// Mitsubishi GX Works2 project: 实例训练(搬运)   PLC: FX3U/FX3UC

PROGRAM MAIN
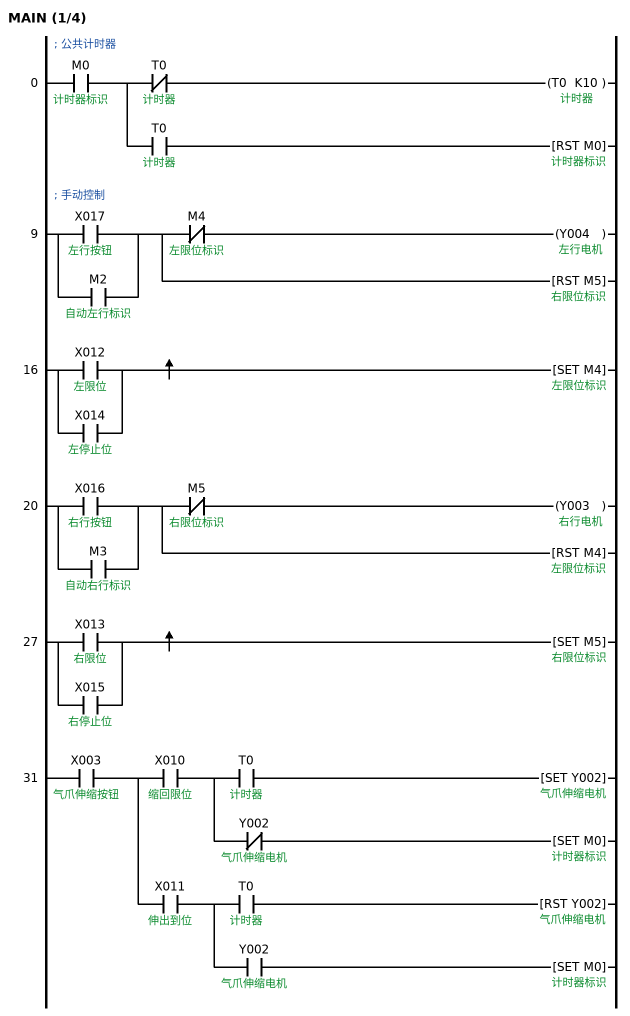
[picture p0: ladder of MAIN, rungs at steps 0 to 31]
; 公共计时器
0     LD      M0  ; 计时器标识
      MPS
      ANI     T0  ; 计时器
      OUT     T0 K10  ; 计时器
      MPP
      AND     T0  ; 计时器
      RST     M0  ; 计时器标识
; 手动控制
9     LD      X017  ; 左行按钮
      OR      M2  ; 自动左行标识
      MPS
      ANI     M4  ; 左限位标识
      OUT     Y004  ; 左行电机
      MPP
      RST     M5  ; 右限位标识
16    LD      X012  ; 左限位
      OR      X014  ; 左停止位
      MEP
      SET     M4  ; 左限位标识
20    LD      X016  ; 右行按钮
      OR      M3  ; 自动右行标识
      MPS
      ANI     M5  ; 右限位标识
      OUT     Y003  ; 右行电机
      MPP
      RST     M4  ; 左限位标识
27    LD      X013  ; 右限位
      OR      X015  ; 右停止位
      MEP
      SET     M5  ; 右限位标识
31    LD      X003  ; 气爪伸缩按钮
      MPS
      AND     X010  ; 缩回限位
      MPS
      AND     T0  ; 计时器
      SET     Y002  ; 气爪伸缩电机
      MPP
      ANI     Y002  ; 气爪伸缩电机
      SET     M0  ; 计时器标识
        [note] 伸缩间隔1秒
      MPP
      AND     X011  ; 伸出到位
      MPS
      AND     T0  ; 计时器
      RST     Y002  ; 气爪伸缩电机
      MPP
      AND     Y002  ; 气爪伸缩电机
      SET     M0  ; 计时器标识
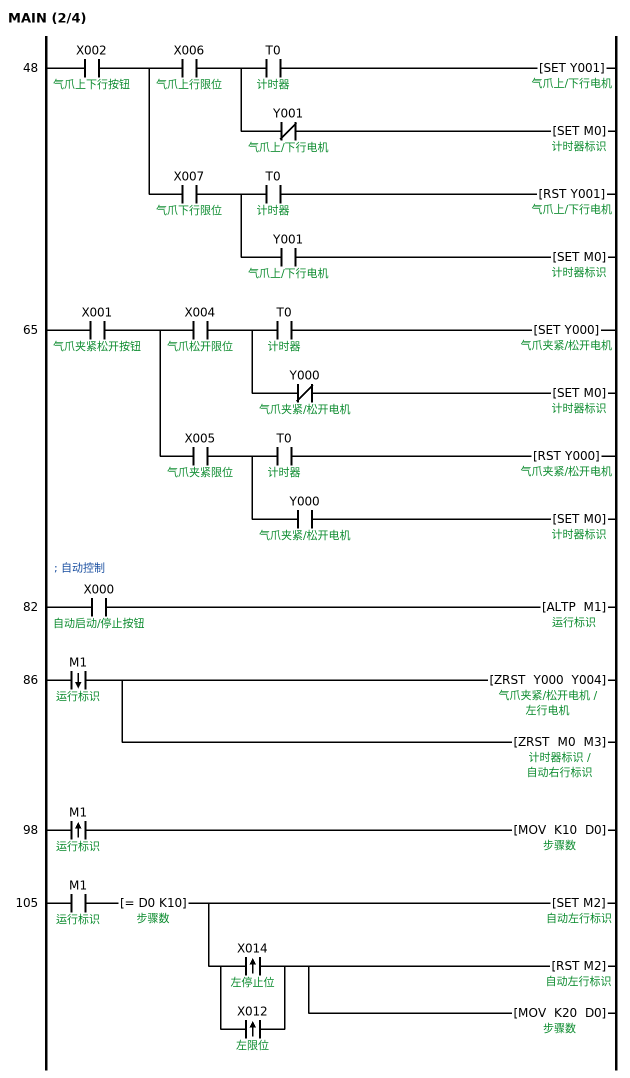
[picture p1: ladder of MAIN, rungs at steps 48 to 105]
48    LD      X002  ; 气爪上下行按钮
      MPS
      AND     X006  ; 气爪上行限位
      MPS
      AND     T0  ; 计时器
      SET     Y001  ; 气爪上/下行电机
      MPP
      ANI     Y001  ; 气爪上/下行电机
      SET     M0  ; 计时器标识
      MPP
      AND     X007  ; 气爪下行限位
      MPS
      AND     T0  ; 计时器
      RST     Y001  ; 气爪上/下行电机
      MPP
      AND     Y001  ; 气爪上/下行电机
      SET     M0  ; 计时器标识
65    LD      X001  ; 气爪夹紧松开按钮
      MPS
      AND     X004  ; 气爪松开限位
      MPS
      AND     T0  ; 计时器
      SET     Y000  ; 气爪夹紧/松开电机
      MPP
      ANI     Y000  ; 气爪夹紧/松开电机
      SET     M0  ; 计时器标识
      MPP
      AND     X005  ; 气爪夹紧限位
      MPS
      AND     T0  ; 计时器
      RST     Y000  ; 气爪夹紧/松开电机
      MPP
      AND     Y000  ; 气爪夹紧/松开电机
      SET     M0  ; 计时器标识
; 自动控制
82    LD      X000  ; 自动启动/停止按钮
      ALTP    M1  ; 运行标识
86    LDF     M1  ; 运行标识
      ZRST    Y000 Y004
      ZRST    M0 M3
98    LDP     M1  ; 运行标识
      MOV     K10 D0  ; 步骤数
105   LD      M1  ; 运行标识
      AND=    D0 K10  ; 步骤数
      SET     M2  ; 自动左行标识
        [note] 1.左行
      LDP     X014  ; 左停止位
      ORP     X012  ; 左限位
      ANB
      RST     M2  ; 自动左行标识
      MOV     K20 D0
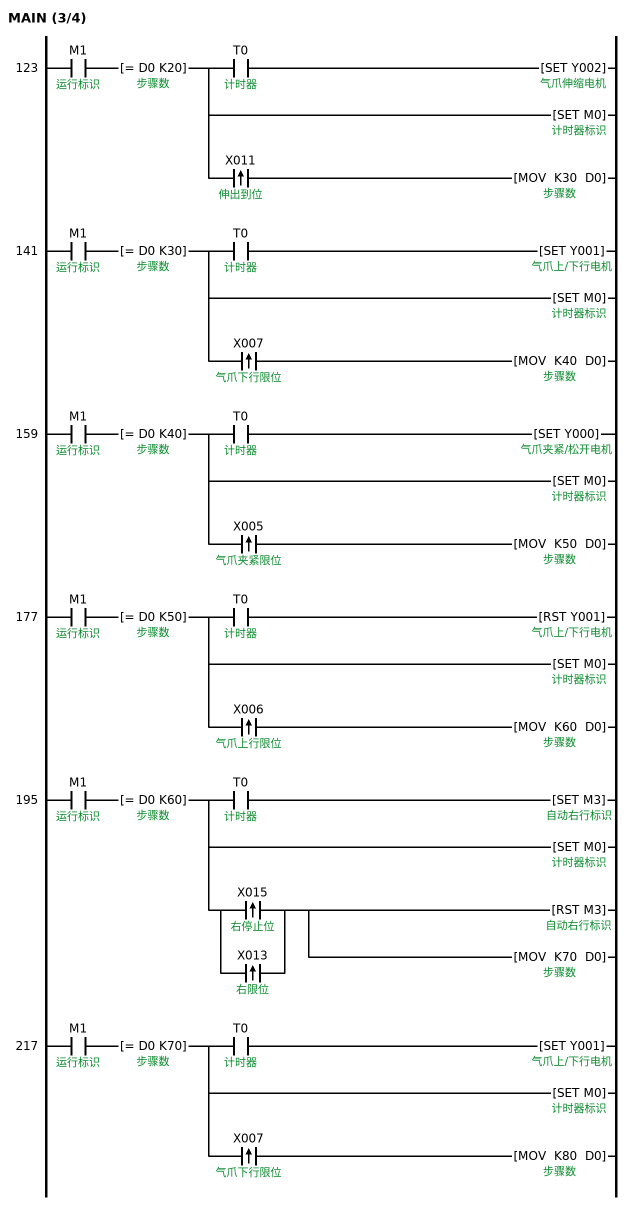
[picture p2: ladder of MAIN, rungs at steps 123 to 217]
123   LD      M1  ; 运行标识
      AND=    D0 K20  ; 步骤数
      MPS
      AND     T0  ; 计时器
      SET     Y002  ; 气爪伸缩电机
        [note] 2.气爪伸出
      MPP
      SET     M0  ; 计时器标识
      ANDP    X011  ; 伸出到位
      MOV     K30 D0
141   LD      M1  ; 运行标识
      AND=    D0 K30  ; 步骤数
      MPS
      AND     T0  ; 计时器
      SET     Y001  ; 气爪上/下行电机
        [note] 3.气爪下行
      MPP
      SET     M0  ; 计时器标识
      ANDP    X007  ; 气爪下行限位
      MOV     K40 D0
159   LD      M1  ; 运行标识
      AND=    D0 K40  ; 步骤数
      MPS
      AND     T0  ; 计时器
      SET     Y000  ; 气爪夹紧/松开电机
        [note] 4.夹紧
      MPP
      SET     M0  ; 计时器标识
      ANDP    X005  ; 气爪夹紧限位
      MOV     K50 D0
177   LD      M1  ; 运行标识
      AND=    D0 K50  ; 步骤数
      MPS
      AND     T0  ; 计时器
      RST     Y001  ; 气爪上/下行电机
        [note] 5.气爪上行
      MPP
      SET     M0  ; 计时器标识
      ANDP    X006  ; 气爪上行限位
      MOV     K60 D0
195   LD      M1  ; 运行标识
      AND=    D0 K60  ; 步骤数
      MPS
      AND     T0  ; 计时器
      SET     M3  ; 自动右行标识
        [note] 6.右行
      MPP
      SET     M0  ; 计时器标识
      LDP     X015  ; 右停止位
      ORP     X013  ; 右限位
      ANB
      RST     M3  ; 自动右行标识
      MOV     K70 D0
217   LD      M1  ; 运行标识
      AND=    D0 K70  ; 步骤数
      MPS
      AND     T0  ; 计时器
      SET     Y001  ; 气爪上/下行电机
        [note] 7.气爪下行
      MPP
      SET     M0  ; 计时器标识
      ANDP    X007  ; 气爪下行限位
      MOV     K80 D0
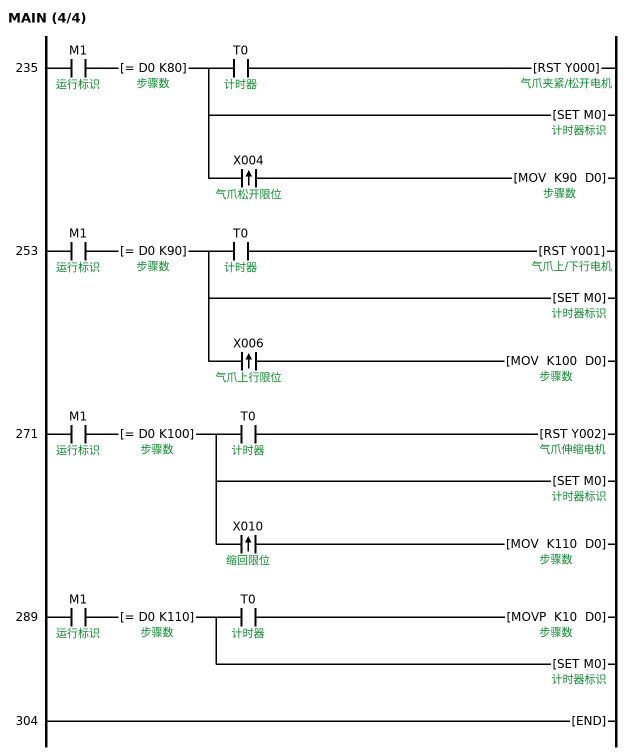
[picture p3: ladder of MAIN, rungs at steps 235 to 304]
235   LD      M1  ; 运行标识
      AND=    D0 K80  ; 步骤数
      MPS
      AND     T0  ; 计时器
      RST     Y000  ; 气爪夹紧/松开电机
        [note] 8.松开
      MPP
      SET     M0  ; 计时器标识
      ANDP    X004  ; 气爪松开限位
      MOV     K90 D0
253   LD      M1  ; 运行标识
      AND=    D0 K90  ; 步骤数
      MPS
      AND     T0  ; 计时器
      RST     Y001  ; 气爪上/下行电机
        [note] 9.气爪上行
      MPP
      SET     M0  ; 计时器标识
      ANDP    X006  ; 气爪上行限位
      MOV     K100 D0
271   LD      M1  ; 运行标识
      AND=    D0 K100  ; 步骤数
      MPS
      AND     T0  ; 计时器
      RST     Y002  ; 气爪伸缩电机
        [note] 10.气爪缩回
      MPP
      SET     M0  ; 计时器标识
      ANDP    X010  ; 缩回限位
      MOV     K110 D0
289   LD      M1  ; 运行标识
      AND=    D0 K110  ; 步骤数
      MPS
      AND     T0  ; 计时器
      MOVP    K10 D0
        [note] 11.回到第一步
      MPP
      SET     M0  ; 计时器标识
304   END
END_PROGRAM
